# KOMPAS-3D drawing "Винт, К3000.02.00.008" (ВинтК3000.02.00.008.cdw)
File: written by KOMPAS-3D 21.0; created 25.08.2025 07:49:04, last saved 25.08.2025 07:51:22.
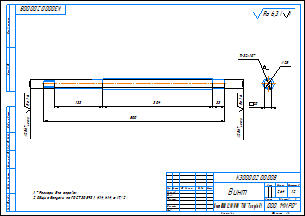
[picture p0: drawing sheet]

Sheet 1: A3, landscape

Document properties: Автор: admin; Полное имя файла: C:\Users\ShavarinML\Desktop\Стапель\2D\ВинтК3000.02.00.008.cdw; Знак неуказанной шероховатости: 4; Параметр неуказанной шероховатости: Ra 6,3; Масса: 2.642347

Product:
- Part/product: Винт  | designation К3000.02.00.008
    Материал: Сталь 35 ГОСТ 1050-2013 (density 7826 kg/m3)
    Масса: 2.642347

Title block, sheet 1: Наименование: Винт; designation: К3000.02.00.008; Материал: Винт ШВП 3210 ("ООО" "ТКП" "Техпривод"); Масса: 2,64; Количество листов документа: 1; organisation: ООО "МИРО"; Форматы листов документа: A3

Views: Спереди 1, Спереди, Проекционный вид 2, Вид:1
Referenced files in C:\Users\ShavarinML\Desktop\Стапель\Задняя бабака\Из трубы\Ролики\: Винт 2.m3d
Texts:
  Ra 1,6
  Tr32x10
  Ra 6,3
  Ra 6,3 ( )
  К3000.02.00.008 Винт
Dimensions and other numbers on the sheet: 33; 304; 133; 500; 25; 20; 1:2; 1; 2,64

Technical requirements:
  *Размеры для справок.
  Общие допуски по ГОСТ 30893.1: H14, h14,   IT/2.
